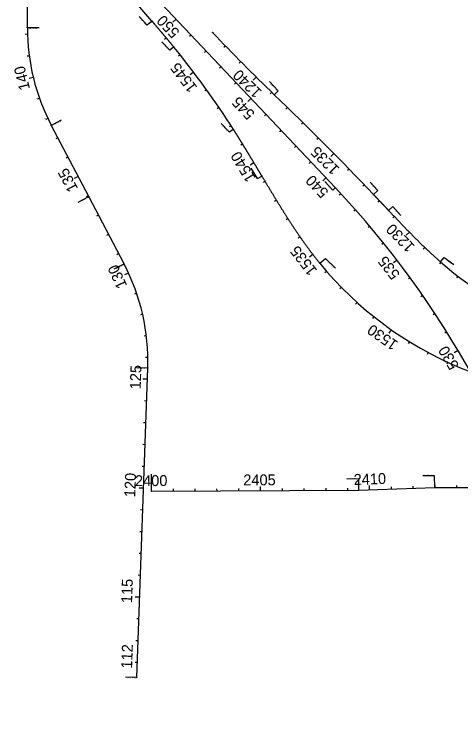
# Model space of a CAD drawing. Extents: x 448091 to 665917, y 1461380 to 1587607.
# Drawn here: x 479484 to 481533, y 1568719 to 1571956 of the extents above; entities that cross this region are included whole.
import ezdxf

# ---------------------------------------------------------------- set-up
doc = ezdxf.new("R2010")
doc.units = 0
for name, color, linetype in [('AttenuatorTM', 7, 'Continuous'), ('BillboardVeg', 7, 'Continuous'), ('BillboardZone', 7, 'Continuous'), ('BLSurvey_dp', 7, 'Continuous'), ('BLSurveyCntrl_ep', 7, 'Continuous'), ('BLSurveyField_ep', 7, 'Continuous'), ('BLSurveySymbl_ep', 7, 'Continuous')]:
    doc.layers.add(name, color=color, linetype=linetype)

msp = doc.modelspace()

# ---------------------------------------------------------------- linework, layer by layer
at = {"layer": 'AttenuatorTM'}
for p, q in [((480094.7, 1571905.8), (480057.7, 1571945)), ((480115.3, 1571923.2), (480094.7, 1571905.8)), ((479545.7, 1571894.1), (479599.4, 1571893.9)), ((480197.6, 1571790.4), (480161.4, 1571828.7)), ((480214.9, 1571804.5), (480197.6, 1571790.4)), ((480694.5, 1571604.7), (480655.1, 1571646.4)), ((480694.5, 1571604.7), (480676.9, 1571586.4)), ((479654.9, 1571446.8), (479701.7, 1571471.4)), ((480471, 1571414.7), (480432.8, 1571455.1)), ((480489, 1571426.2), (480471, 1571414.7)), ((480600.4, 1571201.6), (480570.6, 1571250)), ((480600.4, 1571201.6), (480570.8, 1571249.7)), ((480600.4, 1571201.6), (480620, 1571213.3)), ((480946.2, 1571149), (480908.4, 1571189.1)), ((481151.9, 1571146.8), (481116.8, 1571185.4)), ((480956.5, 1571158.7), (480946.2, 1571149)), ((479825.3, 1571118.7), (479775.5, 1571092.5)), ((481151.9, 1571146.8), (481132.4, 1571128.3)), ((481201.9, 1571056.3), (481220, 1571073.5)), ((481220, 1571073.5), (481257.3, 1571032.5)), ((480886.1, 1570814.4), (480912, 1570835.6)), ((480957.2, 1570790.7), (480912, 1570835.6)), ((481439.6, 1570820.6), (481456.2, 1570839.7)), ((481456.2, 1570839.7), (481499.9, 1570808.3)), ((479987.3, 1570809.8), (479941.7, 1570785.9)), ((480095.9, 1570332.7), (480045.3, 1570334.5)), ((480114.3, 1569769), (480113.9, 1569846.3)), ((481064, 1569824.1), (481009.8, 1569823.8)), ((481064.3, 1569773.1), (481064, 1569824.1)), ((481411.1, 1569838.6), (481358.8, 1569838.2)), ((481412.5, 1569785.8), (481411.1, 1569838.6))]:
    msp.add_line(p, q, dxfattribs=at)
for centre, radius in [((480116, 1571923.9), 1), ((479544.9, 1571894.1), 0.75), ((480393.9, 1571872), 1), ((480215.7, 1571805.2), 1), ((480676.9, 1571586.4), 1), ((479654.2, 1571446.5), 0.75), ((480489.9, 1571426.7), 1), ((480620, 1571213.3), 1), ((480957.2, 1571159.4), 1), ((479826, 1571119), 0.75), ((481132.4, 1571128.3), 1), ((481201.1, 1571055.7), 1), ((479987.9, 1570810.2), 0.75), ((480885.3, 1570813.8), 1), ((481438.9, 1570819.9), 1), ((480096.6, 1570332.7), 0.75), ((480114.3, 1569768), 1), ((481064.3, 1569772.1), 1), ((481412.5, 1569784.8), 1)]:
    msp.add_circle(centre, radius, dxfattribs=at)
at = {"layer": 'BillboardVeg'}
msp.add_line((480957.2, 1571159.4), (479883.3, 1572295.9), dxfattribs=at)
msp.add_arc((477904.7, 1568274.7), 4200, 344.7261, 43.3814, dxfattribs=at)
at = {"layer": 'BLSurvey_dp'}
for p, q in [((480226.7, 1571932.5), (480212.2, 1571918.7)), ((480295.4, 1571859.8), (480288.1, 1571852.9)), ((480364.1, 1571787.1), (480356.8, 1571780.2)), ((480432.7, 1571714.4), (480425.5, 1571707.6)), ((480501.4, 1571641.7), (480494.2, 1571634.9)), ((480570.1, 1571569.1), (480555.6, 1571555.3)), ((480638.8, 1571496.4), (480631.5, 1571489.5)), ((480707.5, 1571423.7), (480700.2, 1571416.8)), ((480776.2, 1571351), (480768.9, 1571344.2)), ((480844.9, 1571278.3), (480837.6, 1571271.5)), ((480913.5, 1571205.7), (480899, 1571191.9)), ((480982.1, 1571132.9), (480974.8, 1571126.1)), ((481049.3, 1571058.8), (481041.8, 1571052.2)), ((481114.7, 1570983.1), (481107, 1570976.7)), ((481178.2, 1570906), (481170.5, 1570899.7)), ((481240, 1570827.3), (481224.1, 1570815.1)), ((481299.8, 1570747.1), (481291.7, 1570741.3)), ((481357.7, 1570665.6), (481349.5, 1570659.9)), ((481413.6, 1570582.7), (481405.3, 1570577.2)), ((481467.6, 1570498.5), (481459.1, 1570493.2)), ((481519.5, 1570413.1), (481502.3, 1570402.9))]:
    msp.add_line(p, q, dxfattribs=at)
at = {"layer": 'BLSurveyCntrl_ep'}
for p, q in [((479544.9, 1571894.1), (479551.8, 1573588.6)), ((480116, 1571923.9), (479889.3, 1572190.5)), ((479826, 1571119), (479654.2, 1571446.5)), ((479987.9, 1570810.2), (479826, 1571119)), ((480046.5, 1568913.8), (480096.6, 1570332.7)), ((480114.3, 1569768), (481064.3, 1569772.1)), ((481064.3, 1569772.1), (481412.5, 1569784.8)), ((481412.5, 1569784.8), (483054.5, 1569787.1))]:
    msp.add_line(p, q, dxfattribs=at)
for centre, radius, start, end in [((480500.3, 1571890.2), 955.4, 179.7681, 207.676), ((486571.7, 1577710.2), 8500, 223.38139, 226.09191), ((477119.1, 1569273.2), 4000, 32.5737, 39.2713), ((470472.7, 1560985.6), 14714, 43.57609, 46.09191), ((479141.9, 1570366.4), 955.4, 357.976, 27.676), ((482154.2, 1571848.1), 1637, 219.1832, 275.7515), ((482571.9, 1572120.6), 1725, 228.9449, 271.1184)]:
    msp.add_arc(centre, radius, start, end, dxfattribs=at)
for points in [[(480116, 1571923.9), (480117.4, 1571922.3), (480118.7, 1571920.7), (480120.1, 1571919.1), (480121.5, 1571917.5), (480122.8, 1571915.9), (480124.2, 1571914.3), (480125.5, 1571912.7), (480126.9, 1571911.1), (480128.2, 1571909.5), (480129.6, 1571907.9), (480131, 1571906.3), (480132.3, 1571904.7), (480133.7, 1571903.1), (480135, 1571901.5), (480136.4, 1571899.9), (480137.7, 1571898.3), (480139.1, 1571896.8), (480140.4, 1571895.2), (480141.8, 1571893.6), (480143.2, 1571892), (480144.5, 1571890.4), (480145.9, 1571888.8), (480147.2, 1571887.2), (480148.6, 1571885.6), (480149.9, 1571884), (480151.3, 1571882.4), (480152.6, 1571880.8), (480154, 1571879.2), (480155.3, 1571877.6), (480156.7, 1571876), (480158, 1571874.4), (480159.4, 1571872.8), (480160.7, 1571871.2), (480162.1, 1571869.6), (480163.4, 1571868), (480164.8, 1571866.4), (480166.1, 1571864.8), (480167.5, 1571863.2), (480168.8, 1571861.6), (480170.2, 1571860), (480171.5, 1571858.4), (480172.9, 1571856.8), (480174.2, 1571855.1), (480175.6, 1571853.5), (480176.9, 1571851.9), (480178.3, 1571850.3), (480179.6, 1571848.7), (480181, 1571847.1), (480182.3, 1571845.5), (480183.6, 1571843.9), (480185, 1571842.3), (480186.3, 1571840.7), (480187.7, 1571839.1), (480189, 1571837.5), (480190.4, 1571835.9), (480191.7, 1571834.3), (480193, 1571832.6), (480194.4, 1571831), (480195.7, 1571829.4), (480197, 1571827.8), (480198.4, 1571826.2), (480199.7, 1571824.6), (480201.1, 1571823), (480202.4, 1571821.4), (480203.7, 1571819.7), (480205.1, 1571818.1), (480206.4, 1571816.5), (480207.7, 1571814.9), (480209, 1571813.3), (480210.4, 1571811.6), (480211.7, 1571810), (480213, 1571808.4), (480214.4, 1571806.8), (480215.7, 1571805.2)], [(480620, 1571213.3), (480618.3, 1571216.2), (480616.6, 1571219.1), (480614.8, 1571222), (480613.1, 1571224.9), (480611.4, 1571227.8), (480609.7, 1571230.7), (480607.9, 1571233.6), (480606.2, 1571236.5), (480604.5, 1571239.4), (480602.7, 1571242.3), (480601, 1571245.2), (480599.3, 1571248.1), (480597.5, 1571251), (480595.8, 1571253.9), (480594.1, 1571256.8), (480592.3, 1571259.7), (480590.6, 1571262.6), (480588.9, 1571265.5), (480587.1, 1571268.4), (480585.4, 1571271.3), (480583.7, 1571274.2), (480581.9, 1571277.1), (480580.2, 1571280), (480578.5, 1571282.9), (480576.7, 1571285.8), (480575, 1571288.7), (480573.2, 1571291.6), (480571.5, 1571294.5), (480569.8, 1571297.4), (480568, 1571300.3), (480566.3, 1571303.2), (480564.5, 1571306.1), (480562.8, 1571309), (480561, 1571311.9), (480559.3, 1571314.7), (480557.5, 1571317.6), (480555.8, 1571320.5), (480554, 1571323.4), (480552.3, 1571326.3), (480550.5, 1571329.2), (480548.8, 1571332.1), (480547, 1571335), (480545.2, 1571337.8), (480543.5, 1571340.7), (480541.7, 1571343.6), (480540, 1571346.5), (480538.2, 1571349.4), (480536.4, 1571352.3), (480534.7, 1571355.1), (480532.9, 1571358), (480531.1, 1571360.9), (480529.3, 1571363.8), (480527.6, 1571366.6), (480525.8, 1571369.5), (480524, 1571372.4), (480522.2, 1571375.3), (480520.5, 1571378.1), (480518.7, 1571381), (480516.9, 1571383.9), (480515.1, 1571386.7), (480513.3, 1571389.6), (480511.5, 1571392.5), (480509.7, 1571395.3), (480507.9, 1571398.2), (480506.1, 1571401), (480504.3, 1571403.9), (480502.5, 1571406.8), (480500.7, 1571409.6), (480498.9, 1571412.5), (480497.1, 1571415.3), (480495.3, 1571418.2), (480493.5, 1571421), (480491.7, 1571423.9), (480489.9, 1571426.7)], [(480620, 1571213.3), (480623.3, 1571207.7), (480626.7, 1571202.2), (480630, 1571196.6), (480633.3, 1571191), (480636.6, 1571185.4), (480640, 1571179.9), (480643.3, 1571174.3), (480646.6, 1571168.7), (480649.9, 1571163.2), (480653.3, 1571157.6), (480656.6, 1571152), (480660, 1571146.5), (480663.3, 1571140.9), (480666.6, 1571135.4), (480670, 1571129.8), (480673.3, 1571124.3), (480676.7, 1571118.7), (480680.1, 1571113.2), (480683.4, 1571107.6), (480686.8, 1571102.1), (480690.2, 1571096.6), (480693.6, 1571091), (480697, 1571085.5), (480700.4, 1571080), (480703.8, 1571074.5), (480707.2, 1571068.9), (480710.6, 1571063.4), (480714.1, 1571057.9), (480717.5, 1571052.4), (480721, 1571046.9), (480724.4, 1571041.4), (480727.9, 1571036), (480731.4, 1571030.5), (480734.8, 1571025), (480738.3, 1571019.6), (480741.8, 1571014.1), (480745.4, 1571008.6), (480748.9, 1571003.2), (480752.4, 1570997.8), (480756, 1570992.3), (480759.5, 1570986.9), (480763.1, 1570981.5), (480766.7, 1570976.1), (480770.3, 1570970.7), (480773.9, 1570965.3), (480777.5, 1570959.9), (480781.2, 1570954.6), (480784.8, 1570949.2), (480788.5, 1570943.8), (480792.2, 1570938.5), (480795.8, 1570933.2), (480799.6, 1570927.8), (480803.3, 1570922.5), (480807, 1570917.2), (480810.8, 1570911.9), (480814.5, 1570906.7), (480818.3, 1570901.4), (480822.1, 1570896.1), (480825.9, 1570890.9), (480829.8, 1570885.7), (480833.6, 1570880.4), (480837.5, 1570875.2), (480841.4, 1570870), (480845.3, 1570864.8), (480849.2, 1570859.7), (480853.1, 1570854.5), (480857.1, 1570849.4), (480861, 1570844.3), (480865, 1570839.1), (480869, 1570834), (480873.1, 1570829), (480877.1, 1570823.9), (480881.2, 1570818.8), (480885.3, 1570813.8)], [(481201.1, 1571055.7), (481200.2, 1571056.6), (481199.3, 1571057.6), (481198.4, 1571058.6), (481197.4, 1571059.6), (481196.5, 1571060.6), (481195.6, 1571061.5), (481194.7, 1571062.5), (481193.7, 1571063.5), (481192.8, 1571064.5), (481191.9, 1571065.5), (481190.9, 1571066.5), (481190, 1571067.4), (481189.1, 1571068.4), (481188.2, 1571069.4), (481187.2, 1571070.4), (481186.3, 1571071.4), (481185.4, 1571072.4), (481184.4, 1571073.3), (481183.5, 1571074.3), (481182.6, 1571075.3), (481181.7, 1571076.3), (481180.7, 1571077.3), (481179.8, 1571078.2), (481178.9, 1571079.2), (481177.9, 1571080.2), (481177, 1571081.2), (481176.1, 1571082.2), (481175.2, 1571083.2), (481174.2, 1571084.1), (481173.3, 1571085.1), (481172.4, 1571086.1), (481171.4, 1571087.1), (481170.5, 1571088.1), (481169.6, 1571089), (481168.7, 1571090), (481167.7, 1571091), (481166.8, 1571092), (481165.9, 1571093), (481164.9, 1571093.9), (481164, 1571094.9), (481163.1, 1571095.9), (481162.2, 1571096.9), (481161.2, 1571097.9), (481160.3, 1571098.9), (481159.4, 1571099.8), (481158.4, 1571100.8), (481157.5, 1571101.8), (481156.6, 1571102.8), (481155.6, 1571103.8), (481154.7, 1571104.7), (481153.8, 1571105.7), (481152.9, 1571106.7), (481151.9, 1571107.7), (481151, 1571108.7), (481150.1, 1571109.6), (481149.1, 1571110.6), (481148.2, 1571111.6), (481147.3, 1571112.6), (481146.3, 1571113.6), (481145.4, 1571114.5), (481144.5, 1571115.5), (481143.6, 1571116.5), (481142.6, 1571117.5), (481141.7, 1571118.5), (481140.8, 1571119.4), (481139.8, 1571120.4), (481138.9, 1571121.4), (481138, 1571122.4), (481137, 1571123.4), (481136.1, 1571124.3), (481135.2, 1571125.3), (481134.2, 1571126.3), (481133.3, 1571127.3), (481132.4, 1571128.3)], [(481201.1, 1571055.7), (481204.3, 1571052.4), (481207.4, 1571049.1), (481210.5, 1571045.8), (481213.6, 1571042.5), (481216.7, 1571039.2), (481219.8, 1571035.9), (481222.9, 1571032.6), (481226, 1571029.3), (481229.1, 1571026.1), (481232.3, 1571022.8), (481235.4, 1571019.5), (481238.5, 1571016.2), (481241.6, 1571012.9), (481244.7, 1571009.6), (481247.9, 1571006.4), (481251, 1571003.1), (481254.1, 1570999.8), (481257.2, 1570996.5), (481260.4, 1570993.3), (481263.5, 1570990), (481266.6, 1570986.7), (481269.8, 1570983.5), (481272.9, 1570980.2), (481276, 1570976.9), (481279.2, 1570973.7), (481282.3, 1570970.4), (481285.5, 1570967.2), (481288.6, 1570963.9), (481291.8, 1570960.7), (481295, 1570957.4), (481298.1, 1570954.2), (481301.3, 1570951), (481304.5, 1570947.7), (481307.6, 1570944.5), (481310.8, 1570941.3), (481314, 1570938.1), (481317.2, 1570934.9), (481320.4, 1570931.6), (481323.6, 1570928.4), (481326.8, 1570925.2), (481330, 1570922), (481333.2, 1570918.8), (481336.4, 1570915.7), (481339.6, 1570912.5), (481342.8, 1570909.3), (481346.1, 1570906.1), (481349.3, 1570902.9), (481352.5, 1570899.8), (481355.8, 1570896.6), (481359, 1570893.5), (481362.3, 1570890.3), (481365.5, 1570887.2), (481368.8, 1570884.1), (481372.1, 1570880.9), (481375.4, 1570877.8), (481378.6, 1570874.7), (481381.9, 1570871.6), (481385.2, 1570868.5), (481388.5, 1570865.4), (481391.8, 1570862.3), (481395.2, 1570859.2), (481398.5, 1570856.1), (481401.8, 1570853.1), (481405.1, 1570850), (481408.5, 1570847), (481411.8, 1570843.9), (481415.2, 1570840.9), (481418.6, 1570837.8), (481421.9, 1570834.8), (481425.3, 1570831.8), (481428.7, 1570828.8), (481432.1, 1570825.8), (481435.5, 1570822.8), (481438.9, 1570819.9)]]:
    msp.add_spline(points, degree=3, dxfattribs=at)
at = {"layer": 'BLSurveyField_ep'}
for p, q in [((480117.2, 1571922.5), (480109.6, 1571916.1)), ((479545.3, 1571863.5), (479535.3, 1571863.2)), ((480181.7, 1571846.2), (480174.1, 1571839.8)), ((480453.3, 1571809.7), (480446.1, 1571802.8)), ((480245.1, 1571768.8), (480237.3, 1571762.6)), ((479553.3, 1571763.9), (479543.4, 1571762.6)), ((480523.2, 1571738.2), (480516.1, 1571731.1)), ((480306.5, 1571689.9), (480290.5, 1571677.8)), ((479571.7, 1571665.6), (479552.2, 1571660.9)), ((480593.8, 1571667.4), (480579.8, 1571653.2)), ((480365.9, 1571609.4), (480357.8, 1571603.6)), ((480665.4, 1571597.5), (480658.4, 1571590.3)), ((479600.2, 1571569.9), (479590.8, 1571566.5)), ((480423.3, 1571527.6), (480415, 1571521.9)), ((480737.2, 1571528), (480730.2, 1571520.8)), ((479638.6, 1571477.6), (479629.6, 1571473.2)), ((480478.6, 1571444.3), (480470.2, 1571438.8)), ((480808.6, 1571458), (480801.6, 1571450.9)), ((479684.5, 1571388.7), (479675.6, 1571384.1)), ((480879.6, 1571387.5), (480872.5, 1571380.4)), ((480531.9, 1571359.6), (480523.4, 1571354.4)), ((480950, 1571316.5), (480935.8, 1571302.5)), ((479730.9, 1571300.2), (479722.1, 1571295.5)), ((480583.7, 1571274.1), (480566.6, 1571263.8)), ((481020, 1571245.1), (481012.8, 1571238.1)), ((479777.4, 1571211.6), (479759.7, 1571202.3)), ((480635, 1571188.2), (480626.4, 1571183.1)), ((481089.5, 1571173.2), (481082.3, 1571166.2)), ((479823.8, 1571123), (479815, 1571118.4)), ((480686.5, 1571102.6), (480678, 1571097.4)), ((481158.5, 1571100.8), (481151.2, 1571093.9)), ((479870.3, 1571034.5), (479861.4, 1571029.8)), ((481227.2, 1571028.1), (481219.9, 1571021.3)), ((480739.5, 1571017.7), (480731.1, 1571012.3)), ((479916.7, 1570945.9), (479907.9, 1570941.3)), ((480794.9, 1570934.5), (480786.7, 1570928.8)), ((481296.4, 1570956), (481282.1, 1570942)), ((481367.3, 1570885.5), (481360.4, 1570878.3)), ((479963.2, 1570857.4), (479954.3, 1570852.7)), ((480853.8, 1570853.7), (480837.9, 1570841.5)), ((481441.1, 1570818), (481434.5, 1570810.4)), ((480008.6, 1570768.3), (479990.5, 1570759.9)), ((480916.9, 1570776.2), (480909.4, 1570769.6)), ((481518.5, 1570754.6), (481512.3, 1570746.7)), ((480984.7, 1570702.6), (480977.5, 1570695.6)), ((480045.9, 1570675.5), (480036.4, 1570672.3)), ((481056.8, 1570633.4), (481050.1, 1570625.9)), ((480073.2, 1570579.4), (480063.5, 1570577.2)), ((481133, 1570568.6), (481126.7, 1570560.8)), ((481213, 1570508.7), (481201.5, 1570492.3)), ((480090.4, 1570480.9), (480080.4, 1570479.7)), ((481296.5, 1570453.7), (481291.3, 1570445.2)), ((480097.1, 1570381.2), (480087.1, 1570381)), ((481383.2, 1570404), (481378.5, 1570395.1)), ((481472.8, 1570359.6), (481468.7, 1570350.5)), ((480094.8, 1570281.2), (480074.8, 1570281.9)), ((480091.3, 1570181.3), (480081.3, 1570181.7)), ((480087.8, 1570081.4), (480077.8, 1570081.7)), ((480084.2, 1569981.4), (480074.2, 1569981.8)), ((480080.7, 1569881.5), (480070.7, 1569881.8)), ((481114.2, 1569774), (481113.5, 1569793.9)), ((481414, 1569784.8), (481414, 1569794.8)), ((481514, 1569784.9), (481514, 1569794.9)), ((480077.2, 1569781.6), (480057.2, 1569782.3)), ((480114.3, 1569768), (480114.2, 1569788)), ((480214.3, 1569768.4), (480214.2, 1569778.4)), ((480314.3, 1569768.9), (480314.2, 1569778.9)), ((480414.3, 1569769.3), (480414.2, 1569779.3)), ((480514.3, 1569769.7), (480514.2, 1569779.7)), ((480614.3, 1569770.2), (480614.2, 1569790.2)), ((480714.3, 1569770.6), (480714.2, 1569780.6)), ((480814.3, 1569771), (480814.2, 1569781)), ((480914.3, 1569771.5), (480914.2, 1569781.5)), ((481014.3, 1569771.9), (481014.2, 1569781.9)), ((481214.2, 1569777.6), (481213.8, 1569787.6)), ((481314.1, 1569781.2), (481313.7, 1569791.2)), ((480073.6, 1569681.6), (480063.6, 1569682)), ((480070.1, 1569581.7), (480060.1, 1569582)), ((480066.6, 1569481.7), (480056.6, 1569482.1)), ((480063, 1569381.8), (480053, 1569382.2)), ((480063.7, 1569401.8), (480060.7, 1569401.9)), ((480059.5, 1569281.9), (480039.5, 1569282.6)), ((480056, 1569181.9), (480046, 1569182.3)), ((480052.4, 1569082), (480042.5, 1569082.3)), ((480048.9, 1568982.1), (480038.9, 1568982.4)), ((480045.8, 1568913.8), (479994.8, 1568915.6))]:
    msp.add_line(p, q, dxfattribs=at)
msp.add_circle((480046.5, 1568913.8), 0.75, dxfattribs=at)

# ---------------------------------------------------------------- texts
at = {"layer": 'AttenuatorTM'}
for s, rotation, p in [('ST STA. 1548+01.76', 133.3814, (480093.4, 1571905.6)), ('PT STA. 142+30.55', 359.7681, (479548.3, 1571888.3)), ('CS STA. 1546+46.76', 132.2723, (480195.9, 1571789.8)), ('PRC STA 1238+83.97', 133.2986, (480692.4, 1571605)), ('PC STA. 137+65.20', 27.676, (479660.9, 1571443.9)), ('SC STA. 1541+79.17', 133.3814, (480465.6, 1571417.9)), ('SRS STA. 1539+29.17', 121.6284, (480597.9, 1571202.5)), ('PT STA. 539+36.39', 133.3814, (480943.4, 1571150)), ('SC STA 1232+37.88', 132.2915, (481150.2, 1571147.1)), ('POT STA. 133+95.44', 207.676, (479824.8, 1571116.8)), ('SRS STA 1231+37.88', 132.2925, (481256.2, 1571032.4)), ('CS STA 1228+02.88', 144.3965, (481498.4, 1570808)), ('PT STA. 130+46.71', 207.676, (479986.8, 1570808)), ('CS STA. 1534+49.17', 135.1928, (480951.7, 1570793.7)), ('PC STA. 125+51.48', 177.976, (480094.6, 1570331.4)), ('PI STA 2400+00.00', 90.2505, (480113.1, 1569793.8)), ('PI STA 2409+50.00', 0.2505, (481011.6, 1569825.5)), ('PI STA 2412+98.49', 0.5867, (481360.6, 1569840.5))]:
    msp.add_text(s, height=3.5, rotation=rotation, dxfattribs=at).set_placement(p)
at = {"layer": 'BillboardZone'}
for s, rotation, p in [('550', 133.3814, (480246.2, 1571874.8)), ('545', 133.3814, (480591.1, 1571501)), ('540', 133.3814, (480929.3, 1571141.6)), ('535', 127.4282, (481256, 1570763)), ('530', 120.6072, (481525.9, 1570343.9))]:
    msp.add_text(s, height=50, rotation=rotation, dxfattribs=at).set_placement(p)
at = {"layer": 'BLSurveySymbl_ep'}
for s, height, rotation, p in [('140', 50, 103.5947, (479557, 1571613.4)), ('1545', 50, 127.1691, (480326.2, 1571620.3)), ('1240', 50, 135.3098, (480623.4, 1571601.5)), ('139', 5, 109.592, (479593.9, 1571562.3)), ('138', 5, 115.5892, (479633.1, 1571469.4)), ('1235', 50, 134.5968, (480979.3, 1571248.2)), ('1540', 50, 120.9269, (480593.3, 1571204.1)), ('135', 50, 117.676, (479778.1, 1571156.1)), ('1230', 50, 134.3239, (481324.6, 1570892.9)), ('1535', 50, 127.4985, (480875.9, 1570780.7)), ('130', 50, 114.8746, (480003.3, 1570711)), ('1530', 50, 144.9043, (481248.4, 1570451)), ('125', 50, 87.976, (480064.1, 1570234.4)), ('120', 50, 87.976, (480039.2, 1569739.6)), ('2400', 50, 0.2505, (480038.3, 1569791.2)), ('2405', 50, 0.2505, (480534.9, 1569794.7)), ('2410', 50, 2.0801, (481041.7, 1569796.3)), ('115', 50, 87.976, (480024.6, 1569253.9)), ('112', 50, 87.976, (480024.7, 1568953.7)), ('POT STA. 111+31.72', 3.5, 177.976, (480044.5, 1568912.5))]:
    msp.add_text(s, height=height, rotation=rotation, dxfattribs=at).set_placement(p)

doc.saveas('drawing.dxf')
